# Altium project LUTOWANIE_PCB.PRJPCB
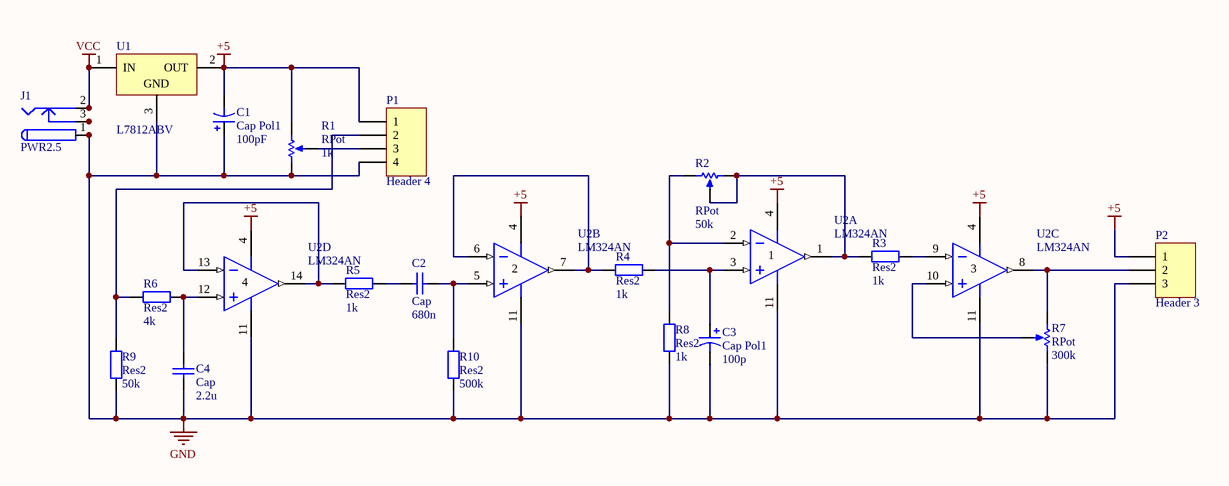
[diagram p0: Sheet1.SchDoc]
1 sheet, 19 parts. Net scope: global (net labels, ports and power ports of the same name join across sheets).
Board file: PCB1.PcbDoc

## Sheet Sheet1.SchDoc
size A4

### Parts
C1  Cap Pol1  value 100pF  [RB7.6-15]
C2  Cap  value 680n  [RAD-0.3]
C3  Cap Pol1  value 100p  [RB7.6-15]
C4  Cap  value 2.2u  [RAD-0.3]
J1  PWR2.5  [KLD-0202]
P1  Header 4  [HDR1X4]
P2  Header 3  [HDR1X3]
R1  RPot  value 1k  [VR5]
R2  RPot  value 50k  [VR5]
R3  Res2  value 1k  [AXIAL-0.4]
R4  Res2  value 1k  [AXIAL-0.4]
R5  Res2  value 1k  [AXIAL-0.4]
R6  Res2  value 4k  [AXIAL-0.4]
R7  RPot  value 300k  [VR5]
R8  Res2  value 1k  [AXIAL-0.4]
R9  Res2  value 50k  [AXIAL-0.4]
R10  Res2  value 500k  [AXIAL-0.4]
U1  L7812ABV  [TO220ABN]
U2  LM324AN  [N14A]  (parts A,B,C,D of 4)

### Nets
+5: C1.2 P1.1 P2.1 R1.2(BOT) U1.2(OUT) U2.4(V+)
GND: C1.1 C3.2 C4.1 J1.1 J1.1A J1.1B P1.4 P2.3 R1.1(TOP) R7.2(BOT) R8.2 R9.1 R10.2 U1.3(GND) U2.11(GND)
VCC: J1.2 J1.2A J1.2B U1.1(IN)
NetC2_1: C2.1 R10.1 U2.5(IN+)
NetC2_2: C2.2 R5.1
NetC3_1: C3.1 R4.1 U2.3(IN+)
NetC4_2: C4.2 R6.1 U2.12(IN+)
NetJ1_3: J1.3 J1.3A J1.3B
NetP1_2: P1.2 R6.2 R9.2
NetP1_3: P1.3 R1.3(TAP)
NetP2_2: P2.2 R7.1(TOP) U2.8(OUT)
NetR2_1: R2.1(TOP) R8.1 U2.2(IN-)
NetR2_2: R2.2(BOT) R2.3(TAP) R3.2 U2.1(OUT)
NetR3_1: R3.1 U2.9(IN-)
NetR4_2: R4.2 U2.6(IN-) U2.7(OUT)
NetR5_2: R5.2 U2.13(IN-) U2.14(OUT)
NetR7_3: R7.3(TAP) U2.10(IN+)

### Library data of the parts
C1 C3 = Cap Pol1: Polarized Capacitor (Radial)
C2 C4 = Cap: Capacitor
J1 = PWR2.5: Low Voltage Power Supply Connector
P1 = Header 4: Header, 4-Pin
P2 = Header 3: Header, 3-Pin
R1 R2 R7 = RPot: Potentiometer; Sim Note: Enter the Resistance value and the set point into parameter fields.; Set Position: 0.5
R3-R6 R8-R10 = Res2: Resistor
U1 = L7812ABV: Precision 1A Regulator
U2 = LM324AN: Low-Power Quad Operational Amplifier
